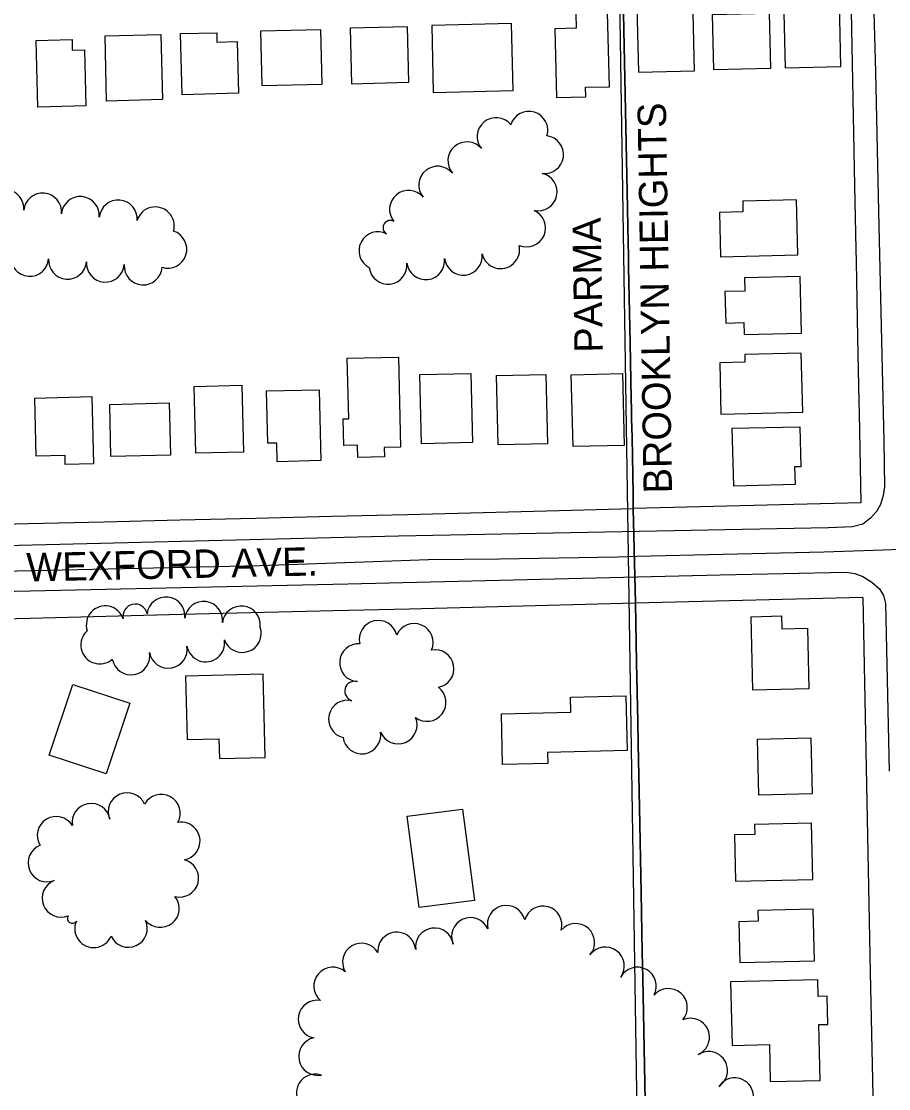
# Model space of a CAD drawing. Extents: x -25029 to 2274964, y -81170 to 687028.
# Drawn here: x -16618 to -16160, y -66160 to -65597 of the extents above; entities that cross this region are included whole.
import ezdxf

# ---------------------------------------------------------------- set-up
doc = ezdxf.new("R2010")
doc.units = 0
for name, color, linetype in [('81911BEA - RW_X_Fee_RW', 7, 'Continuous'), ('BLDG', 7, 'Continuous'), ('DIVISIONS', 7, 'Continuous'), ('DV_X_Corp_Line', 7, 'Continuous'), ('GE_X_CL_2000', 7, 'Continuous'), ('ROAD', 7, 'Continuous'), ('ROAD-NAME', 7, 'Continuous'), ('TREES', 7, 'Continuous')]:
    doc.layers.add(name, color=color, linetype=linetype)

msp = doc.modelspace()

# ---------------------------------------------------------------- linework, layer by layer
at = {"layer": '81911BEA - RW_X_Fee_RW'}
for p, q in [((-16174.87, -65850.78), (-16294.95, -65853.72)), ((-16173.87, -65900.78), (-16293.73, -65903.7))]:
    msp.add_line(p, q, dxfattribs=at)
for points in [[(-16180.58, -65563.56), (-16178.19, -65683.53), (-16177.53, -65717.01)], [(-16177.53, -65717.01), (-16177.4, -65723.52), (-16176.6, -65763.52), (-16175.93, -65797.44), (-16175.81, -65803.51), (-16174.87, -65850.78)], [(-17173.84, -65875.4), (-17133.85, -65874.43), (-17093.86, -65873.45), (-17013.88, -65871.5), (-16973.89, -65870.52), (-16933.9, -65869.55), (-16893.92, -65868.57), (-16853.93, -65867.6), (-16773.95, -65865.65), (-16693.97, -65863.7), (-16653.98, -65862.72), (-16613.99, -65861.75), (-16574, -65860.77), (-16534.01, -65859.8), (-16494.02, -65858.82), (-16454.03, -65857.85), (-16414.04, -65856.87), (-16374.05, -65855.89), (-16334.06, -65854.92), (-16294.95, -65853.72)], [(-16173.87, -65900.78), (-16172.63, -65963.48), (-16171.73, -66008.47), (-16170.83, -66053.46), (-16169.94, -66098.45), (-16168.65, -66163.44), (-16165.16, -66338.4)], [(-16293.73, -65903.7), (-16373.06, -65905.89), (-16413.04, -65906.86), (-16453.03, -65907.84), (-16533.01, -65909.79), (-16612.99, -65911.74), (-16692.97, -65913.69), (-16772.95, -65915.64), (-16812.93, -65916.61), (-16852.92, -65917.59), (-16932.9, -65919.54), (-17012.88, -65921.49), (-17092.86, -65923.44), (-17173.3, -65925.4)]]:
    msp.add_lwpolyline(points, dxfattribs=at)
at = {"layer": 'BLDG'}
for points in [[(-16262.56, -65622.89), (-16263.29, -65592.48), (-16270.55, -65592.66), (-16270.64, -65588.66), (-16293, -65589.2), (-16292.17, -65623.6)], [(-16209.68, -65587.6), (-16209.57, -65592.08), (-16215.57, -65592.22), (-16214.87, -65621.31), (-16185.38, -65620.6), (-16186.19, -65587.04)], [(-16319.93, -65636.6), (-16320.05, -65631.57), (-16307.51, -65631.26), (-16308.45, -65592.19), (-16325.28, -65592.59), (-16325.09, -65600.45), (-16336.26, -65600.72), (-16335.39, -65636.97)], [(-16253.18, -65593.15), (-16223.33, -65592.43), (-16222.63, -65621.69), (-16252.48, -65622.41)], [(-16490.73, -65630.66), (-16459, -65629.89), (-16459.69, -65601.21), (-16491.43, -65601.97)], [(-16443.54, -65629.65), (-16413.31, -65628.92), (-16414.01, -65599.6), (-16444.25, -65600.33)], [(-16400.36, -65634.29), (-16358.23, -65633.27), (-16359.09, -65597.87), (-16401.21, -65598.88)], [(-16590.89, -65606.37), (-16590.76, -65611.91), (-16584.28, -65611.75), (-16583.57, -65641.42), (-16608.91, -65642.03), (-16609.76, -65606.82)], [(-16543.26, -65638.08), (-16572.64, -65638.79), (-16573.47, -65604.42), (-16544.09, -65603.71)], [(-16514.58, -65602.74), (-16514.46, -65607.7), (-16503.73, -65607.44), (-16503.07, -65634.74), (-16532.85, -65635.45), (-16533.63, -65603.2)], [(-16237.22, -65691.56), (-16237.09, -65697.28), (-16249.43, -65697.58), (-16248.87, -65720.97), (-16208.16, -65719.99), (-16208.86, -65690.88)], [(-16236.32, -65732.05), (-16236.15, -65739.08), (-16246.56, -65739.33), (-16246.16, -65755.92), (-16236.54, -65755.69), (-16236.38, -65762.02), (-16206.18, -65761.29), (-16206.9, -65731.34)], [(-16418.76, -65773.87), (-16417.61, -65821.48), (-16426.28, -65821.69), (-16426.16, -65826.5), (-16440.16, -65826.84), (-16440.32, -65820.41), (-16447.56, -65820.59), (-16447.9, -65806.53), (-16444.97, -65806.46), (-16445.74, -65774.52)], [(-16236.16, -65772.52), (-16236.07, -65776.57), (-16249.32, -65776.89), (-16248.67, -65803.97), (-16205.58, -65802.93), (-16206.33, -65771.8)], [(-16380.56, -65782.5), (-16379.68, -65818.96), (-16406.62, -65819.61), (-16407.5, -65783.15)], [(-16300.56, -65782.61), (-16299.65, -65820.51), (-16326.69, -65821.16), (-16327.6, -65783.26)], [(-16340.98, -65783.04), (-16340.1, -65819.64), (-16366.13, -65820.26), (-16367.01, -65783.67)], [(-16501.39, -65788.78), (-16500.54, -65824.06), (-16525.65, -65824.67), (-16526.5, -65789.39)], [(-16460.6, -65791.11), (-16459.7, -65828.53), (-16482.63, -65829.08), (-16482.86, -65819.24), (-16487.62, -65819.35), (-16488.28, -65791.77)], [(-16580.39, -65794.76), (-16579.54, -65830.15), (-16594.48, -65830.51), (-16594.59, -65825.83), (-16609.82, -65826.19), (-16610.56, -65795.49)], [(-16539.66, -65798.08), (-16539, -65825.57), (-16570.36, -65826.32), (-16571.02, -65798.84)], [(-16206.53, -65831.81), (-16209.81, -65831.89), (-16209.59, -65841.17), (-16241.97, -65841.95), (-16242.71, -65811.49), (-16207.04, -65810.63)], [(-16216.68, -65910.49), (-16216.52, -65917.25), (-16203.12, -65916.92), (-16202.35, -65948.94), (-16231.81, -65949.65), (-16232.74, -65910.88)], [(-16530.18, -65975.67), (-16513.45, -65975.26), (-16513.2, -65985.67), (-16489.07, -65985.09), (-16490.13, -65941.27), (-16530.99, -65942.25)], [(-16560.48, -65956.54), (-16572.85, -65993.86), (-16602.92, -65983.89), (-16590.54, -65946.57)], [(-16298.18, -65981.45), (-16340.12, -65982.46), (-16339.98, -65988.33), (-16363.84, -65988.91), (-16364.48, -65962.19), (-16327.82, -65961.3), (-16328.01, -65953.31), (-16298.87, -65952.61)], [(-16201.29, -65974.83), (-16200.57, -66004.41), (-16228.76, -66005.09), (-16229.47, -65975.51)], [(-16384.97, -66012.4), (-16378.73, -66060.59), (-16407.82, -66064.36), (-16414.07, -66016.17)], [(-16230.99, -66020.46), (-16230.87, -66025.76), (-16241.56, -66026.01), (-16240.97, -66050.48), (-16200.21, -66049.5), (-16200.93, -66019.73)], [(-16229.21, -66065.83), (-16229.07, -66071.57), (-16239.17, -66071.81), (-16238.65, -66093.39), (-16199.31, -66092.44), (-16199.97, -66065.13)], [(-16242.81, -66137.11), (-16223.15, -66136.64), (-16222.68, -66156.15), (-16196.35, -66155.51), (-16197.06, -66126.08), (-16192.35, -66125.97), (-16192.71, -66111.08), (-16197.34, -66111.19), (-16197.56, -66102.44), (-16243.62, -66103.55)]]:
    msp.add_lwpolyline(points, close=True, dxfattribs=at)
at = {"layer": 'DIVISIONS'}
msp.add_line((-16252.4, -68748.36), (-16315.19, -64748.36), dxfattribs=at)
msp.add_line((-16252.4, -68748.36), (-16315.19, -64748.36), dxfattribs=at)
at = {"layer": 'DV_X_Corp_Line'}
for p, q in [((-16298.31, -65678.09), (-16300.53, -65566.49)), ((-16298.31, -65678.09), (-16300.53, -65566.49)), ((-16300.53, -65566.49), (-16298.31, -65678.09)), ((-16300.53, -65566.49), (-16298.31, -65678.09)), ((-16298.16, -65686.46), (-16298.31, -65678.09)), ((-16298.16, -65686.46), (-16298.31, -65678.09)), ((-16298.31, -65678.09), (-16298.16, -65686.46)), ((-16298.31, -65678.09), (-16298.16, -65686.46)), ((-16297.61, -65713.99), (-16298.16, -65686.46)), ((-16297.61, -65713.99), (-16298.16, -65686.46)), ((-16298.16, -65686.46), (-16297.61, -65713.99)), ((-16298.16, -65686.46), (-16297.61, -65713.99)), ((-16297.49, -65720.13), (-16297.61, -65713.99)), ((-16297.49, -65720.13), (-16297.61, -65713.99)), ((-16297.61, -65713.99), (-16297.49, -65720.13)), ((-16297.61, -65713.99), (-16297.49, -65720.13)), ((-16297.37, -65726.45), (-16297.49, -65720.13)), ((-16297.37, -65726.45), (-16297.49, -65720.13)), ((-16297.49, -65720.13), (-16297.37, -65726.45)), ((-16297.49, -65720.13), (-16297.37, -65726.45)), ((-16296.57, -65766.44), (-16297.37, -65726.45)), ((-16296.57, -65766.44), (-16297.37, -65726.45)), ((-16297.37, -65726.45), (-16296.57, -65766.44)), ((-16297.37, -65726.45), (-16296.57, -65766.44)), ((-16295.96, -65796.15), (-16296.57, -65766.44)), ((-16295.96, -65796.15), (-16296.57, -65766.44)), ((-16296.57, -65766.44), (-16295.96, -65796.15)), ((-16296.57, -65766.44), (-16295.96, -65796.15)), ((-16295.87, -65801.16), (-16295.96, -65796.15)), ((-16295.87, -65801.16), (-16295.96, -65796.15)), ((-16295.96, -65796.15), (-16295.87, -65801.16)), ((-16295.96, -65796.15), (-16295.87, -65801.16)), ((-16295.77, -65806.44), (-16295.87, -65801.16)), ((-16295.77, -65806.44), (-16295.87, -65801.16)), ((-16295.87, -65801.16), (-16295.77, -65806.44)), ((-16295.87, -65801.16), (-16295.77, -65806.44)), ((-16295.67, -65811.29), (-16295.77, -65806.44)), ((-16295.67, -65811.29), (-16295.77, -65806.44)), ((-16295.77, -65806.44), (-16295.67, -65811.29)), ((-16295.77, -65806.44), (-16295.67, -65811.29)), ((-16295.56, -65816.15), (-16295.67, -65811.29)), ((-16295.56, -65816.15), (-16295.67, -65811.29)), ((-16295.67, -65811.29), (-16295.56, -65816.15)), ((-16295.67, -65811.29), (-16295.56, -65816.15)), ((-16295.36, -65826.15), (-16295.56, -65816.15)), ((-16295.36, -65826.15), (-16295.56, -65816.15)), ((-16295.56, -65816.15), (-16295.36, -65826.15)), ((-16295.56, -65816.15), (-16295.36, -65826.15)), ((-16294.96, -65846.14), (-16295.36, -65826.15)), ((-16294.96, -65846.14), (-16295.36, -65826.15)), ((-16295.36, -65826.15), (-16294.96, -65846.14)), ((-16295.36, -65826.15), (-16294.96, -65846.14)), ((-16294.95, -65849.91), (-16294.96, -65846.14)), ((-16294.95, -65849.91), (-16294.96, -65846.14)), ((-16294.96, -65846.14), (-16294.95, -65849.91)), ((-16294.96, -65846.14), (-16294.95, -65849.91)), ((-16294.95, -65853.72), (-16294.95, -65849.91)), ((-16294.95, -65853.72), (-16294.95, -65849.91)), ((-16294.95, -65849.91), (-16294.95, -65853.72)), ((-16294.95, -65849.91), (-16294.95, -65853.72)), ((-16293.73, -65903.7), (-16294.95, -65853.72)), ((-16293.73, -65903.7), (-16294.95, -65853.72)), ((-16294.95, -65853.72), (-16293.73, -65903.7)), ((-16294.95, -65853.72), (-16293.73, -65903.7)), ((-16293.16, -65935.05), (-16293.73, -65903.7)), ((-16293.16, -65935.05), (-16293.73, -65903.7)), ((-16293.73, -65903.7), (-16293.16, -65935.05)), ((-16293.73, -65903.7), (-16293.16, -65935.05)), ((-16292.59, -65966.4), (-16293.16, -65935.05)), ((-16292.59, -65966.4), (-16293.16, -65935.05)), ((-16293.16, -65935.05), (-16292.59, -65966.4)), ((-16293.16, -65935.05), (-16292.59, -65966.4)), ((-16292.33, -65978.03), (-16292.59, -65966.4)), ((-16292.33, -65978.03), (-16292.59, -65966.4)), ((-16292.59, -65966.4), (-16292.33, -65978.03)), ((-16292.59, -65966.4), (-16292.33, -65978.03)), ((-16291.7, -66011.4), (-16292.33, -65978.03)), ((-16291.7, -66011.4), (-16292.33, -65978.03)), ((-16292.33, -65978.03), (-16291.7, -66011.4)), ((-16292.33, -65978.03), (-16291.7, -66011.4)), ((-16290.8, -66056.39), (-16291.7, -66011.4)), ((-16290.8, -66056.39), (-16291.7, -66011.4)), ((-16291.7, -66011.4), (-16290.8, -66056.39)), ((-16291.7, -66011.4), (-16290.8, -66056.39)), ((-16290.14, -66088.01), (-16290.8, -66056.39)), ((-16290.14, -66088.01), (-16290.8, -66056.39)), ((-16290.8, -66056.39), (-16290.14, -66088.01)), ((-16290.8, -66056.39), (-16290.14, -66088.01)), ((-16289.91, -66101.38), (-16290.14, -66088.01)), ((-16289.91, -66101.38), (-16290.14, -66088.01)), ((-16290.14, -66088.01), (-16289.91, -66101.38)), ((-16290.14, -66088.01), (-16289.91, -66101.38)), ((-16288.61, -66166.36), (-16289.91, -66101.38)), ((-16288.61, -66166.36), (-16289.91, -66101.38)), ((-16289.91, -66101.38), (-16288.61, -66166.36)), ((-16289.91, -66101.38), (-16288.61, -66166.36))]:
    msp.add_line(p, q, dxfattribs=at)
at = {"layer": 'GE_X_CL_2000'}
for points in [[(-16149.62, -65875.2), (-16163.13, -65875.75), (-16194.34, -65876.9), (-16293.29, -65879.16)], [(-16293.29, -65879.16), (-16303.05, -65879.42), (-16365.46, -65880.44), (-16402.82, -65880.92), (-16431.87, -65881.85), (-16491.88, -65884.05), (-16627.92, -65887.07), (-16693.28, -65889.4), (-16754.45, -65890.45), (-16811.27, -65891.69), (-16941.23, -65895.06), (-17012.35, -65897.04), (-17070.04, -65897.79), (-17139.01, -65899.45), (-17198.69, -65901.33), (-17268.78, -65902.34), (-17340.41, -65904.16), (-17408.69, -65905.83), (-17472.73, -65907.2), (-17532.98, -65908.58), (-17591.96, -65910.12), (-17635.29, -65911.09), (-17691.96, -65912.64), (-17736.22, -65913.93)]]:
    msp.add_lwpolyline(points, dxfattribs=at)
at = {"layer": 'ROAD'}
for points in [[(-16169.01, -65560.69), (-16167.12, -65623.33), (-16165.62, -65697.17), (-16162.78, -65818.34), (-16162.51, -65842.36), (-16163.21, -65846.9), (-16164.63, -65851.72), (-16166.71, -65855.37), (-16169.81, -65858.93), (-16173.94, -65861.98), (-16179.37, -65863.41), (-16192.04, -65864.04), (-16418.69, -65868.38), (-16711.94, -65875.67), (-17068.56, -65884.39), (-17320.2, -65890.44), (-17579.9, -65896.66), (-17817.96, -65902.24)], [(-17260.97, -65913.15), (-17071.15, -65907.95), (-16850.13, -65902.55), (-16668.97, -65898.47), (-16445.39, -65893.6), (-16249.06, -65888.82), (-16182.62, -65887.41), (-16178.01, -65888.03), (-16173.78, -65889.67), (-16169.18, -65892.7), (-16165.11, -65896.1), (-16162.94, -65899.64), (-16161.94, -65903.89), (-16159.96, -65992.38)]]:
    msp.add_lwpolyline(points, dxfattribs=at)
at = {"layer": 'TREES'}
for centre, radius, start, end in [((-16367.28, -65657.61), 10, 39.1722, 219.1722), ((-16349.97, -65654.24), 10, 342.8784, 162.8784), ((-16341.69, -65667.1), 10, 262.6653, 82.6653), ((-16382.67, -65670.38), 10, 40.1977, 220.1977), ((-16398.01, -65683.21), 10, 39.5782, 219.5782), ((-16345.11, -65686.79), 10, 257.6091, 77.6091), ((-16626.31, -65695.56), 10, 354.795, 174.795), ((-16413.43, -65695.95), 10, 39.5782, 219.5782), ((-16606.4, -65697.38), 10, 354.795, 174.795), ((-16586.48, -65699.19), 10, 354.795, 174.795), ((-16566.56, -65701.01), 10, 354.795, 174.795), ((-16546.99, -65704.68), 10, 343.9178, 163.9178), ((-16351.18, -65705.75), 10, 246.871, 66.871), ((-16423.06, -65705.6), 3.81, 59.5764, 239.5764), ((-16540.38, -65716.99), 10, 252.5691, 72.5691), ((-16429.58, -65717.77), 10, 62.7118, 242.7118), ((-16364.85, -65717.21), 10, 193.0777, 13.0777), ((-16613.18, -65721.29), 10, 175.6355, 355.6355), ((-16384.52, -65720.67), 10, 186.8822, 6.8822), ((-16593.24, -65722.81), 10, 175.6355, 355.6355), ((-16573.29, -65724.34), 10, 175.6355, 355.6355), ((-16553.35, -65725.82), 10, 175.8739, 355.8739), ((-16424.23, -65725.46), 10, 186.8822, 6.8822), ((-16404.38, -65723.07), 10, 186.8822, 6.8822), ((-16541.35, -65910.48), 10, 353.2312, 173.2312), ((-16573.37, -65915.17), 10, 18.3299, 198.3299), ((-16557.58, -65910.66), 6.45, 12.1732, 192.1732), ((-16521.49, -65912.84), 10, 353.2312, 173.2312), ((-16501.63, -65915.2), 10, 353.2312, 173.2312), ((-16501.13, -65919.71), 10, 199.4641, 19.4641), ((-16429.39, -65922.85), 10, 13.4143, 193.4143), ((-16410.48, -65924.49), 10, 336.6654, 156.6654), ((-16576.26, -65925.82), 10, 131.3077, 311.3077), ((-16520.42, -65924.7), 10, 189.5683, 9.5683), ((-16540.14, -65928.03), 10, 189.6097, 9.6097), ((-16439.77, -65935.15), 10, 86.218, 266.218), ((-16399.47, -65938.29), 10, 280.5006, 100.5006), ((-16559.83, -65931.52), 10, 190.4634, 10.4634), ((-16441.85, -65950.16), 5.22, 74.2498, 254.2498), ((-16403.69, -65956.09), 10, 232.8259, 52.8259), ((-16445.61, -65964.9), 10, 76.4353, 256.4353), ((-16418.94, -65967.96), 10, 202.9526, 22.9526), ((-16438.05, -65973.24), 10, 187.9575, 7.9575), ((-16561.79, -66013.72), 10, 23.3212, 203.3212), ((-16543.85, -66014.59), 10, 331.1403, 151.1403), ((-16580.83, -66019.38), 10, 9.7841, 189.7841), ((-16599.22, -66026.29), 10, 31.4147, 211.4147), ((-16533.37, -66029.27), 10, 279.8952, 99.8952), ((-16604.05, -66040.79), 10, 111.7021, 291.7021), ((-16534.13, -66048.81), 10, 255.6837, 75.6837), ((-16596.66, -66059.38), 10, 111.7021, 291.7021), ((-16544.36, -66064.8), 10, 219.1027, 39.1027), ((-16361.87, -66073.22), 10, 13.5501, 193.5501), ((-16342.52, -66073.55), 10, 344.4484, 164.4484), ((-16590.78, -66070.07), 2.59, 147.2135, 327.2135), ((-16380.73, -66079.64), 10, 24.0628, 204.0628), ((-16579.45, -66075.48), 10, 156.3849, 336.3849), ((-16561.2, -66075.3), 10, 204.7421, 24.7421), ((-16399.76, -66085.11), 10, 8.0092, 188.0092), ((-16325.31, -66082.77), 10, 319.2033, 139.2033), ((-16419.63, -66087.3), 10, 4.5668, 184.5668), ((-16438.23, -66093.15), 10, 30.367, 210.367), ((-16309.65, -66095.18), 10, 324.0079, 144.0079), ((-16453.38, -66105.78), 10, 49.2335, 229.2335), ((-16292.76, -66105.81), 10, 331.5961, 151.5961), ((-16276.39, -66117.09), 10, 319.3132, 139.3132), ((-16461.61, -66123.21), 10, 80.239, 260.239), ((-16264.72, -66132.74), 10, 294.0703, 114.0703), ((-16461.35, -66142.87), 10, 101.2496, 281.2496), ((-16255.22, -66150.27), 10, 302.8572, 122.8572), ((-16462.57, -66162.16), 10, 71.516, 251.516), ((-16241.46, -66164.19), 10, 326.4737, 146.4737)]:
    msp.add_arc(centre, radius, start, end, dxfattribs=at)

# ---------------------------------------------------------------- texts
at = {"layer": 'DIVISIONS'}
for s, p in [('BROOKLYN HEIGHTS', (-16274.47, -65845.73)), ('PARMA', (-16310.94, -65771.46))]:
    msp.add_text(s, height=15, rotation=90.8993, dxfattribs=at).set_placement(p)
at = {"layer": 'ROAD-NAME'}
msp.add_text('WEXFORD AVE.', height=15, rotation=1.1981, dxfattribs=at).set_placement((-16614.82, -65892.33))

doc.saveas('drawing.dxf')
